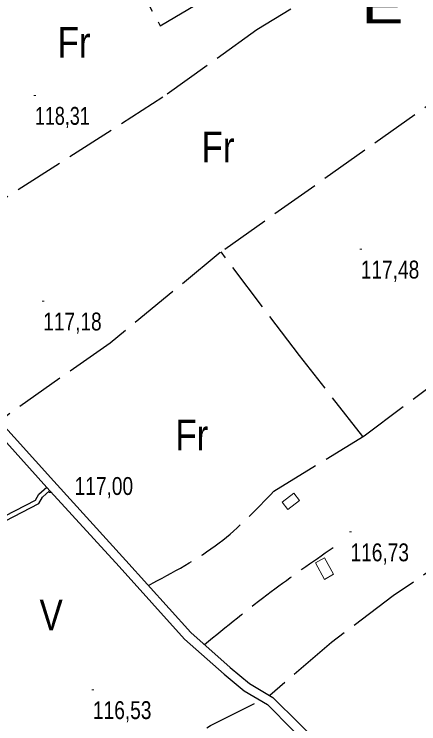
# Model space of a CAD drawing. Extents: x 483855 to 488461, y 4388206 to 4391419.
# Drawn here: x 486774 to 486972, y 4389476.9 to 4389824.2 of the extents above; entities that cross this region are included whole.
import ezdxf
from ezdxf.enums import TextEntityAlignment as Align

# ---------------------------------------------------------------- set-up
doc = ezdxf.new("R2010")
doc.units = 0
doc.header["$LTSCALE"] = 4
doc.linetypes.add('LONG_DASHED', pattern=[7.5, 6, -1.5])
for name, color, linetype, lineweight in [('15', 7, 'LONG_DASHED', 13), ('25', 7, 'LONG_DASHED', 25), ('36', 7, 'Continuous', 25), ('38', 7, 'Continuous', 25), ('47', 7, 'Continuous', 35), ('7', 7, 'Continuous', 13)]:
    doc.layers.add(name, color=color, linetype=linetype, lineweight=lineweight)
doc.layers.add('31', color=7, linetype='Continuous')
doc.layers.add('5', color=7, linetype='Continuous')

msp = doc.modelspace()

# ---------------------------------------------------------------- linework, layer by layer
at = {"layer": '15'}
msp.add_spline([(486600.4, 4389500.4), (486609.53, 4389487.73), (486615.3, 4389473.18), (486624.1, 4389453.89), (486627.18, 4389436.63), (486631.67, 4389416.03), (486632.08, 4389397.56), (486631.95, 4389372.35), (486630.17, 4389353.19), (486626.74, 4389333.85), (486620.21, 4389319.31), (486618.97, 4389312.22), (486616.63, 4389302.9), (486615.3, 4389298.13), (486616.17, 4389293.83), (486619.18, 4389291.58), (486621.18, 4389290.55), (486622.68, 4389290.51), (486634.2, 4389286.38), (486638.07, 4389284.93), (486643.81, 4389278.03), (486647.56, 4389269.23), (486650.39, 4389259.78), (486653.99, 4389251.13), (486656.86, 4389240.47), (486657.77, 4389237.9), (486661.83, 4389229.76), (486671.61, 4389219.08), (486678.78, 4389212.29), (486683.98, 4389207.43), (486692.61, 4389198.65), (486703.14, 4389188.17), (486710.21, 4389183.18), (486715.1, 4389178.1), (486721.79, 4389169.75), (486729.66, 4389154.99), (486739.9, 4389124.93), (486746.35, 4389104.88), (486753.6, 4389089.16), (486760.79, 4389077.19), (486767, 4389065.18), (486770.68, 4389053.83), (486770.87, 4389043.77), (486770.89, 4389027.41), (486771.77, 4389015.38), (486774.63, 4389004.13), (486780.27, 4388993.03), (486790.86, 4388976.17), (486799.95, 4388962.27), (486807.15, 4388950.98), (486807.71, 4388946.54), (486807.28, 4388935.75), (486805.22, 4388922.9), (486805.98, 4388914.7), (486807.94, 4388900.77), (486816.17, 4388882.69), (486824.04, 4388864.93), (486829.16, 4388851.22), (486832.74, 4388836.04), (486834.17, 4388830.45), (486834.92, 4388824.88), (486836.06, 4388816.9), (486838.49, 4388803.4), (486845.1, 4388783.65), (486849.03, 4388767.64), (486849.62, 4388755.09)], degree=3, dxfattribs=at)
at = {"layer": '25'}
for points in [[(486922.38, 4389931.06), (486935.95, 4389908.14), (486948.56, 4389882.68), (486960.66, 4389857.75), (486892.81, 4389816.46), (486846.7, 4389783.53), (486767.8, 4389732.92), (486730.53, 4389782.29)], [(486816.77, 4389871), (486830.13, 4389846.76), (486845.44, 4389818.45), (486886.44, 4389842.66), (486947.22, 4389885.4)], [(487067.88, 4389846.57), (486994.66, 4389792.19), (486874.88, 4389707.53), (486820.98, 4389663.25), (486766.63, 4389625.09)], [(486901.09, 4389590.7), (486945.24, 4389617.84), (487015.8, 4389670.84), (487047.22, 4389695.83), (487137.35, 4389759.8), (487199.98, 4389805.1)], [(486944.67, 4389617.49), (486913.63, 4389657.08), (486875.28, 4389707.82)], [(487043, 4389602.61), (486994.15, 4389563.14), (486959.55, 4389539.51), (486929.24, 4389516.74), (486899.16, 4389490.75)], [(486704.45, 4389536.79), (486725.04, 4389509.32), (486766.5, 4389470.65), (486800.91, 4389432.23), (486842.58, 4389459.51), (486870.1, 4389476.12), (486894.57, 4389488.29)]]:
    msp.add_lwpolyline(points, dxfattribs=at)
at = {"layer": '36'}
for points in [[(486573.3, 4389818.73), (486664.59, 4389729.76), (486701.09, 4389692.46), (486732.39, 4389662.19), (486764.81, 4389627.09), (486793.34, 4389595.58), (486828.71, 4389556.83), (486860.49, 4389521.58), (486879.69, 4389504.55), (486889.19, 4389496.62), (486900.68, 4389489.84), (486913.43, 4389477.11), (486933.6, 4389456.96), (486953.64, 4389433.43), (486986.75, 4389395.23)], [(486570.03, 4389815.48), (486697.95, 4389689.3), (486729.21, 4389659.07), (486761.53, 4389624.08), (486790.05, 4389592.58), (486825.42, 4389553.84), (486857.35, 4389518.41), (486876.78, 4389501.18), (486886.62, 4389492.97), (486897.93, 4389486.3), (486910.28, 4389473.96), (486930.33, 4389453.93), (486950.27, 4389430.53), (486983.41, 4389392.29)]]:
    msp.add_lwpolyline(points, dxfattribs=at)
at = {"layer": '38'}
for points in [[(486578.76, 4389457.48), (486603.48, 4389470.14), (486608.56, 4389474.89), (486611.25, 4389477.14), (486613.54, 4389478.88), (486624.62, 4389486.84), (486658.52, 4389509.44), (486680.26, 4389522.97), (486710.81, 4389543.71), (486745.77, 4389563.43), (486764.4, 4389576), (486784.49, 4389586.29), (486786.08, 4389589.25), (486789.99, 4389592.65)], [(486580.53, 4389454.68), (486604.78, 4389468.42), (486609.99, 4389473.27), (486612.59, 4389475.46), (486614.81, 4389477.15), (486625.85, 4389485.07), (486659.69, 4389507.63), (486681.44, 4389521.17), (486711.95, 4389541.88), (486746.9, 4389561.6), (486765.5, 4389574.14), (486786.08, 4389584.68), (486787.8, 4389587.9), (486791.46, 4389591.04)]]:
    msp.add_lwpolyline(points, dxfattribs=at)
at = {"layer": '38', "linetype": 'LONG_DASHED'}
for points in [[(486839.72, 4389544.65), (486874.32, 4389565.44), (486901.09, 4389590.7)], [(486867.08, 4389515.68), (486899.73, 4389541.59), (486930.08, 4389563.16)]]:
    msp.add_spline(points, degree=3, dxfattribs=at)
at = {"layer": '47', "lineweight": 13}
for points in [[(486913.58, 4389586.25), (486907.91, 4389581.86), (486905.15, 4389585.42), (486910.82, 4389589.81)], [(486925.84, 4389547.59), (486921.49, 4389555.61), (486925.97, 4389558.17), (486930.32, 4389550.15)]]:
    msp.add_lwpolyline(points, close=True, dxfattribs=at)
at = {"layer": '7'}
for p, q in [((486783.65, 4389784.41), (486784.65, 4389784.41)), ((486943.15, 4389709.19), (486944.15, 4389709.19)), ((486787.7, 4389683.77), (486788.7, 4389683.77)), ((486791.03, 4389590.12), (486792.03, 4389590.12)), ((486938.11, 4389570.82), (486939.11, 4389570.82)), ((486812.06, 4389493.6), (486813.06, 4389493.6))]:
    msp.add_line(p, q, dxfattribs=at)

# ---------------------------------------------------------------- texts
at = {"layer": '31', "width": 0.85}
for s, p in [('Fr', (486803.32, 4389802.95)), ('Fr', (486873.76, 4389751.7)), ('Fr', (486860.95, 4389610.75)), ('V', (486792.11, 4389522.65))]:
    msp.add_text(s, height=15, dxfattribs=at).set_placement(p, align=Align.CENTER)
at = {"layer": '5', "width": 1.35}
msp.add_text('E  S     P  L  A', height=16.99, dxfattribs=at).set_placement((487136.65, 4389819.75), align=Align.RIGHT)
at = {"layer": '7'}
for s, width, p in [('118,31', 0.75, (486784.15, 4389770.04)), ('117,48', 0.8, (486943.65, 4389694.82)), ('117,18', 0.8, (486788.2, 4389669.4)), ('117,00', 0.8, (486803.58, 4389588.9)), ('116,73', 0.8, (486938.61, 4389556.45)), ('116,53', 0.8, (486812.56, 4389479.23))]:
    msp.add_text(s, height=8.75, dxfattribs=dict(at, width=width)).set_placement(p)

doc.saveas('drawing.dxf')
